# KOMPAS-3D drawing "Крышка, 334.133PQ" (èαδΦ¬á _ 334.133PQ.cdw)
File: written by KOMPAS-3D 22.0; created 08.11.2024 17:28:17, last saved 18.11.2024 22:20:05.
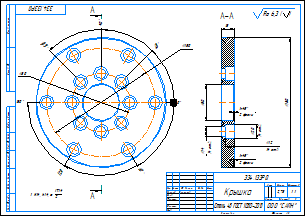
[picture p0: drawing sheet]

Sheet 1: A3, landscape

Document properties: Автор: aleksander.larionov.10@gmail.com; Полное имя файла: C:\Мои папки\Работа\Крышки, фланцы\334.133PQ\Крышка _ 334.133PQ.cdw; Знак неуказанной шероховатости: 4; Параметр неуказанной шероховатости: Ra 6,3; Масса: 2.782462

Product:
- Part/product: Крышка  | designation 334.133PQ
    Материал: Сталь 45 ГОСТ 1050-2013 (density 7810 kg/m3)
    Масса: 2.782462

Title block, sheet 1: Наименование: Крышка; designation: 334.133PQ; Материал: Сталь 45 ГОСТ 1050-2013; Масса: 2,78; Количество листов документа: 1; organisation: ООО "САЙН"; Форматы листов документа: A3; stored path: C:\Users\aleks\Desktop\Работа\Крышки, фланцы\226.1007\Крышка _ 226.1007.cdw; Разработал: Ларионов

Views: Вид 1, Сверху, Разрез А-А
Referenced files in C:\Users\aleks\Desktop\Работа\Крышки, фланцы\226.1007\: Крышка _ 226.1007.m3d
Referenced files in C:\Users\aleks\Desktop\Работа\Крышки, фланцы\334.133PQ\: Крышка _ 334.133PQ.m3d
Referenced files in C:\Мои папки\Работа\Крышки, фланцы\334.133PQ\: Крышка _ 334.133PQ.m3d
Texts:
  Ra 6,3
  Ra 6,3 ( )
Dimensions and other numbers on the sheet: 120; 180; 150; 80; 135; 334.133PQ; 4; 18; 1; 2 фаски; 12; 14 отв.; 14; 20; 50; 1 H14, h14,    IT14 2 .; 1:1; 2,78; 334.133PQ Крышка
